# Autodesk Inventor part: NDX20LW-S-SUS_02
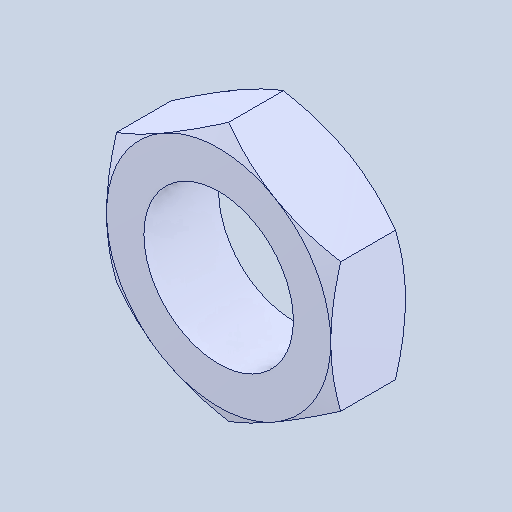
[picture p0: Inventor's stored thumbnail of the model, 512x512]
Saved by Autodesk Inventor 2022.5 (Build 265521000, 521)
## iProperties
Created: 2024-05
Part Number: NDX20LW-S-SUS_02
Material: 一般
Document SubType Name: Modeling
Designer: ImaoCorp
Density: 1 g/cm^3
Appearance: 既定
Author: ImaoCorp
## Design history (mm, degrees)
feature "NDX20LW-S-SUS_02"
node "ソリッド1"
